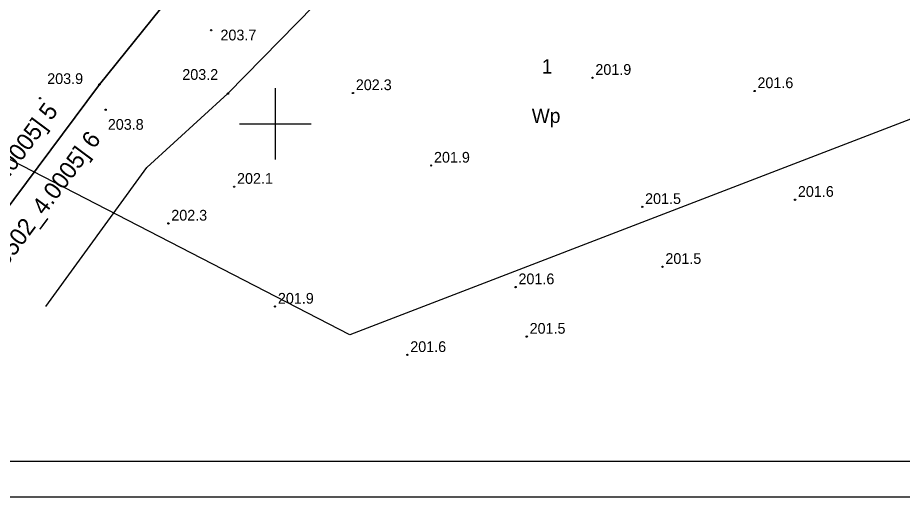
# Model space of a CAD drawing. Extents: x 6512606 to 6513006, y 6022524 to 6022728.
# Drawn here: x 6512732 to 6512793.9, y 6022523.9 to 6022557.4 of the extents above; entities that cross this region are included whole.
import ezdxf

# ---------------------------------------------------------------- set-up
doc = ezdxf.new("R2010")
doc.units = 0
for name, color, linetype in [('203-punkt graniczny', 7, 'Continuous'), ('208-opis obrębu', 7, 'Continuous'), ('210-oznaczenie konturu użytku gruntowego', 7, 'Continuous'), ('211-numer działki ewidencyjnej', 7, 'Continuous'), ('216-obręb ewidencyjny', 7, 'Continuous'), ('217-kontur klasyfikacyjny', 7, 'Continuous'), ('218-kontur użytku gruntowego', 7, 'Continuous'), ('219-działka ewidencyjna', 7, 'Continuous'), ('4', 7, 'Continuous'), ('Default', 7, 'Continuous'), ('maxp_ramka_2', 7, 'Continuous'), ('Obszar opracowania', 7, 'Continuous'), ('pikieta naturalna', 7, 'Continuous'), ('pikieta naturalna-Atr2', 7, 'Continuous'), ('punkt wysokościowy naturalny', 7, 'Continuous'), ('punkt wysokościowy naturalny-Atr2', 7, 'Continuous'), ('woda stojąca', 7, 'Continuous')]:
    doc.layers.add(name, color=color, linetype=linetype)

# ---------------------------------------------------------------- blocks, each defined once
blk = doc.blocks.new('203')
at = {"layer": 'Default'}
blk.add_circle((0, 0), 0.45, dxfattribs=at)
blk = doc.blocks.new('PW01')
at = {"layer": 'Default'}
blk.add_circle((0, 0), 0.45, dxfattribs=at)

msp = doc.modelspace()

# ---------------------------------------------------------------- linework, layer by layer
at = {"layer": '216-obręb ewidencyjny'}
for points in [[(6512728.286, 6022540.131), (6512737.69, 6022552.74), (6512751.08, 6022569.37), (6512775.81, 6022564.08), (6512780.7, 6022581.02), (6512806.2, 6022572.11), (6512806.62, 6022563.51), (6512811.41, 6022558.95), (6512818.47, 6022559.72), (6512828.23, 6022562.62), (6512858.85, 6022571.74), (6512855.78, 6022583.95), (6512853.17, 6022604.51), (6512852.25, 6022608.25), (6512838.47, 6022634.29)], [(6512751.08, 6022569.37), (6512737.69, 6022552.74), (6512728.286, 6022540.131)]]:
    msp.add_lwpolyline(points, dxfattribs=at)
at = {"layer": '217-kontur klasyfikacyjny'}
for points in [[(6512737.69, 6022552.74), (6512751.08, 6022569.37)], [(6512728.286, 6022540.131), (6512737.69, 6022552.74)]]:
    msp.add_lwpolyline(points, dxfattribs=at)
at = {"layer": '218-kontur użytku gruntowego'}
for points in [[(6512737.69, 6022552.74), (6512751.08, 6022569.37)], [(6512751.08, 6022569.37), (6512737.69, 6022552.74)], [(6512728.286, 6022540.131), (6512737.69, 6022552.74)], [(6512737.69, 6022552.74), (6512728.286, 6022540.131)]]:
    msp.add_lwpolyline(points, dxfattribs=at)
at = {"layer": '219-działka ewidencyjna'}
for points in [[(6512737.69, 6022552.74), (6512751.08, 6022569.37)], [(6512737.69, 6022552.74), (6512728.286, 6022540.131)]]:
    msp.add_lwpolyline(points, dxfattribs=at)
at = {"layer": '4'}
for points in [[(6512737.69, 6022552.74), (6512751.08, 6022569.37)], [(6512737.69, 6022552.74), (6512728.286, 6022540.131)]]:
    msp.add_lwpolyline(points, dxfattribs=at)
at = {"layer": 'Default'}
for p, q in [((6512750, 6022547.5), (6512750, 6022552.5)), ((6512747.5, 6022550), (6512752.5, 6022550))]:
    msp.add_line(p, q, dxfattribs=at)
at = {"layer": 'maxp_ramka_2'}
for points in [[(6512605.658, 6022723.882), (6513005.658, 6022723.882), (6513005.658, 6022523.882), (6512605.658, 6022523.882)], [(6512618.158, 6022526.382), (6512618.158, 6022721.382), (6513003.158, 6022721.382), (6513003.158, 6022526.382)]]:
    msp.add_lwpolyline(points, close=True, dxfattribs=at)
at = {"layer": 'Obszar opracowania'}
msp.add_lwpolyline([(6512710.98, 6022693.84), (6512748.35, 6022694.16), (6512798.11, 6022695.25), (6512807.47, 6022695.46), (6512809.66, 6022606.87), (6512863.71, 6022622.03), (6512875.13, 6022581.36), (6512755.22, 6022535.25), (6512691.61, 6022568.03), (6512709.16, 6022605.16)], close=True, dxfattribs=at)
at = {"layer": 'woda stojąca'}
for points in [[(6512741.02, 6022546.93), (6512746.68, 6022552.11), (6512753.93, 6022559.53), (6512757.57, 6022561.69), (6512765.47, 6022568.01), (6512770.86, 6022573.28), (6512769.34, 6022577.71), (6512768.52, 6022578.94)], [(6512733.94, 6022537.22), (6512741.02, 6022546.93)]]:
    msp.add_lwpolyline(points, dxfattribs=at)

# ---------------------------------------------------------------- block references
at = {"layer": '203-punkt graniczny', "xscale": 0.1, "yscale": 0.10000000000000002}
msp.add_blockref('203', (6512737.69, 6022552.74), dxfattribs=at)
at = {"layer": 'pikieta naturalna', "xscale": 0.1, "yscale": 0.10000000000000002}
for p in [(6512745.51, 6022556.54), (6512772.19, 6022553.22), (6512746.68, 6022552.11), (6512755.43, 6022552.15), (6512783.53, 6022552.29), (6512733.54, 6022551.78), (6512760.9, 6022547.08), (6512747.12, 6022545.6), (6512786.36, 6022544.69), (6512775.67, 6022544.19), (6512742.52, 6022543.03), (6512777.09, 6022540), (6512766.81, 6022538.58), (6512749.98, 6022537.22), (6512767.59, 6022535.12), (6512759.24, 6022533.84)]:
    msp.add_blockref('PW01', p, dxfattribs=at)
at = {"layer": 'punkt wysokościowy naturalny', "xscale": 0.1, "yscale": 0.10000000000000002}
msp.add_blockref('PW01', (6512738.13, 6022550.98), dxfattribs=at)

# ---------------------------------------------------------------- texts
at = {"layer": '208-opis obrębu'}
for s, p in [('[220502_4.0005] 5', (6512726.85, 6022540.15)), ('[220502_4.0005] 6', (6512729.84, 6022538.17))]:
    msp.add_text(s, height=1.2, rotation=53.284, dxfattribs=at).set_placement(p)
at = {"layer": '210-oznaczenie konturu użytku gruntowego'}
msp.add_text('Wp', height=1, dxfattribs=at).set_placement((6512767.94, 6022550.06))
at = {"layer": '211-numer działki ewidencyjnej'}
msp.add_text('1', height=1, dxfattribs=at).set_placement((6512768.64, 6022553.51))
at = {"layer": '4'}
msp.add_text('1', height=1, dxfattribs=at).set_placement((6512768.64, 6022553.51))
at = {"layer": 'pikieta naturalna-Atr2'}
for s, p in [('203.7', (6512746.16, 6022555.83)), ('201.9', (6512772.39, 6022553.42)), ('203.9', (6512734.04, 6022552.78)), ('203.2', (6512743.49, 6022553.07)), ('201.6', (6512783.73, 6022552.49)), ('202.3', (6512755.63, 6022552.35)), ('201.9', (6512761.1, 6022547.28)), ('202.1', (6512747.32, 6022545.8)), ('201.6', (6512786.56, 6022544.89)), ('201.5', (6512775.87, 6022544.39)), ('202.3', (6512742.72, 6022543.23)), ('201.5', (6512777.29, 6022540.2)), ('201.6', (6512767.01, 6022538.78)), ('201.9', (6512750.18, 6022537.42)), ('201.5', (6512767.79, 6022535.32)), ('201.6', (6512759.44, 6022534.04))]:
    msp.add_text(s, height=0.75, dxfattribs=at).set_placement(p)
at = {"layer": 'punkt wysokościowy naturalny-Atr2'}
msp.add_text('203.8', height=0.75, dxfattribs=at).set_placement((6512738.28, 6022549.58))

doc.saveas('drawing.dxf')
